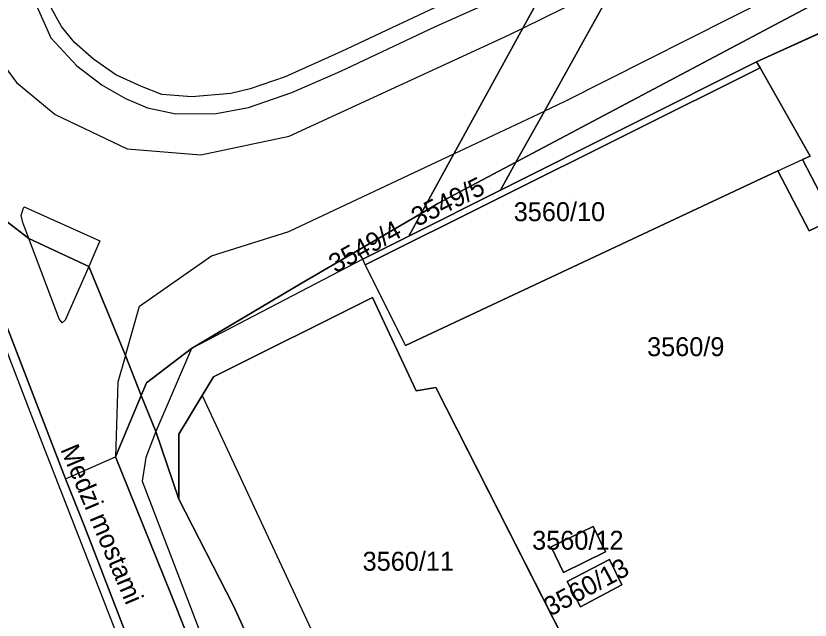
# Model space of a CAD drawing. Extents: x -262657 to -261595, y -1238015 to -1237156.
# Drawn here: x -262558.2 to -262474.2, y -1237300.9 to -1237237.1 of the extents above; entities that cross this region are included whole.
import ezdxf

# ---------------------------------------------------------------- set-up
doc = ezdxf.new("R2010")
doc.units = 0
for name, color, linetype in [('body_kn', 7, 'Continuous'), ('kladpar_druhypozemkov', 7, 'Continuous'), ('kladpar_hranice', 7, 'Continuous'), ('kladpar_parcelnecisla', 7, 'Continuous'), ('kladpar_plochy', 7, 'Continuous'), ('popisy', 7, 'Continuous'), ('zappar_hrandruhpozemk', 7, 'Continuous')]:
    doc.layers.add(name, color=color, linetype=linetype)

msp = doc.modelspace()

# ---------------------------------------------------------------- linework, layer by layer
at = {"layer": 'body_kn'}
for p, q in [((-262553.39, -1237238.2), (-262553.39, -1237238.2)), ((-262518.45, -1237238.33), (-262518.45, -1237238.33)), ((-262513.82, -1237238.2), (-262513.82, -1237238.2)), ((-262504.59, -1237238.36), (-262504.59, -1237238.36)), ((-262504.59, -1237238.36), (-262504.59, -1237238.36)), ((-262554.54, -1237239.38), (-262554.54, -1237239.38)), ((-262506.03, -1237239.07), (-262506.03, -1237239.07)), ((-262552.03, -1237239.9), (-262552.03, -1237239.9)), ((-262523.79, -1237240.82), (-262523.79, -1237240.82)), ((-262551.76, -1237242.35), (-262551.76, -1237242.35)), ((-262550.02, -1237241.66), (-262550.02, -1237241.66)), ((-262479.86, -1237241.92), (-262479.86, -1237241.92)), ((-262523.85, -1237242.92), (-262523.85, -1237242.92)), ((-262479.48, -1237242.55), (-262479.48, -1237242.55)), ((-262547.63, -1237243.31), (-262547.63, -1237243.31)), ((-262529.75, -1237243.5), (-262529.75, -1237243.5)), ((-262558.17, -1237244.12), (-262558.17, -1237244.12)), ((-262549.08, -1237244.4), (-262549.08, -1237244.4)), ((-262544.93, -1237244.55), (-262544.93, -1237244.55)), ((-262533.44, -1237244.78), (-262533.44, -1237244.78)), ((-262542.78, -1237245.39), (-262542.78, -1237245.39)), ((-262539.62, -1237245.64), (-262539.62, -1237245.64)), ((-262535.47, -1237245.28), (-262535.47, -1237245.28)), ((-262529.04, -1237245.18), (-262529.04, -1237245.18)), ((-262546.63, -1237245.81), (-262546.63, -1237245.81)), ((-262500.14, -1237246.11), (-262500.14, -1237246.11)), ((-262500.14, -1237246.11), (-262500.14, -1237246.11)), ((-262544.28, -1237246.79), (-262544.28, -1237246.79)), ((-262537.02, -1237247.38), (-262537.02, -1237247.38)), ((-262533.61, -1237246.77), (-262533.61, -1237246.77)), ((-262502.31, -1237247.13), (-262502.31, -1237247.13)), ((-262554.06, -1237247.5), (-262554.06, -1237247.5)), ((-262541.29, -1237247.44), (-262541.29, -1237247.44)), ((-262529.31, -1237249.79), (-262529.31, -1237249.79)), ((-262546.46, -1237251.13), (-262546.46, -1237251.13)), ((-262538.64, -1237251.75), (-262538.64, -1237251.75)), ((-262511.88, -1237251.65), (-262511.88, -1237251.65)), ((-262511.88, -1237251.65), (-262511.88, -1237251.65)), ((-262474.99, -1237252.26), (-262474.99, -1237252.26)), ((-262474.21, -1237251.89), (-262474.21, -1237251.89)), ((-262505.32, -1237252.54), (-262505.32, -1237252.54)), ((-262477.6, -1237253.45), (-262477.6, -1237253.45)), ((-262477.6, -1237253.45), (-262477.6, -1237253.45)), ((-262506.96, -1237255.49), (-262506.96, -1237255.49)), ((-262506.96, -1237255.49), (-262506.96, -1237255.49)), ((-262557.44, -1237257.47), (-262557.44, -1237257.47)), ((-262557.33, -1237257.26), (-262557.33, -1237257.26)), ((-262513.57, -1237256.92), (-262513.57, -1237256.92)), ((-262557.65, -1237258.17), (-262557.65, -1237258.17)), ((-262515.34, -1237257.95), (-262515.34, -1237257.95)), ((-262515.34, -1237257.95), (-262515.34, -1237257.95)), ((-262557.5, -1237258.9), (-262557.5, -1237258.9)), ((-262529.33, -1237259.88), (-262529.33, -1237259.88)), ((-262474.31, -1237259.79), (-262474.31, -1237259.79)), ((-262556.86, -1237260.6), (-262556.86, -1237260.6)), ((-262556.86, -1237260.6), (-262556.86, -1237260.6)), ((-262549.35, -1237260.86), (-262549.35, -1237260.86)), ((-262516.66, -1237260.35), (-262516.66, -1237260.35)), ((-262516.66, -1237260.35), (-262516.66, -1237260.35)), ((-262537.51, -1237262.43), (-262537.51, -1237262.43)), ((-262522.11, -1237261.89), (-262522.11, -1237261.89)), ((-262521.53, -1237262.79), (-262521.53, -1237262.79)), ((-262521.53, -1237262.79), (-262521.53, -1237262.79)), ((-262521.26, -1237263.38), (-262521.26, -1237263.38)), ((-262521.26, -1237263.38), (-262521.26, -1237263.38)), ((-262550.52, -1237263.55), (-262550.52, -1237263.55)), ((-262550.52, -1237263.55), (-262550.52, -1237263.55)), ((-262527.92, -1237265.28), (-262527.92, -1237265.28)), ((-262520.5, -1237266.83), (-262520.5, -1237266.83)), ((-262545.14, -1237267.77), (-262545.14, -1237267.77)), ((-262553.65, -1237269.09), (-262553.65, -1237269.09)), ((-262553.65, -1237269.09), (-262553.65, -1237269.09)), ((-262553, -1237269.23), (-262553, -1237269.23)), ((-262553.33, -1237269.53), (-262553.33, -1237269.53)), ((-262539.65, -1237272.22), (-262539.65, -1237272.22)), ((-262539.65, -1237272.22), (-262539.65, -1237272.22)), ((-262516.99, -1237271.93), (-262516.99, -1237271.93)), ((-262546.64, -1237272.98), (-262546.64, -1237272.98)), ((-262546.64, -1237272.98), (-262546.64, -1237272.98)), ((-262547.45, -1237275.8), (-262547.45, -1237275.8)), ((-262544.39, -1237275.85), (-262544.39, -1237275.85)), ((-262537.33, -1237275.21), (-262537.33, -1237275.21)), ((-262515.86, -1237276.71), (-262515.86, -1237276.71)), ((-262513.79, -1237276.37), (-262513.79, -1237276.37)), ((-262544.97, -1237277.21), (-262544.97, -1237277.21)), ((-262544.97, -1237277.21), (-262544.97, -1237277.21)), ((-262538.53, -1237277.21), (-262538.53, -1237277.21)), ((-262538.53, -1237277.21), (-262538.53, -1237277.21)), ((-262556.56, -1237279.36), (-262556.56, -1237279.36)), ((-262543.4, -1237280.99), (-262543.4, -1237280.99)), ((-262543.4, -1237280.99), (-262543.4, -1237280.99)), ((-262540.98, -1237281.3), (-262540.98, -1237281.3)), ((-262547.68, -1237283.68), (-262547.68, -1237283.68)), ((-262544.46, -1237283.76), (-262544.46, -1237283.76)), ((-262552.98, -1237286.01), (-262552.98, -1237286.01)), ((-262552.98, -1237286.01), (-262552.98, -1237286.01)), ((-262544.85, -1237286.26), (-262544.85, -1237286.26)), ((-262540.97, -1237288.14), (-262540.97, -1237288.14)), ((-262550.94, -1237291.12), (-262550.94, -1237291.12)), ((-262497.15, -1237291.03), (-262497.15, -1237291.03)), ((-262501.6, -1237293.21), (-262501.6, -1237293.21)), ((-262495.83, -1237293.72), (-262495.83, -1237293.72)), ((-262495.43, -1237294.53), (-262495.43, -1237294.53)), ((-262495.43, -1237294.53), (-262495.43, -1237294.53)), ((-262500.28, -1237295.9), (-262500.28, -1237295.9)), ((-262500.28, -1237295.9), (-262500.28, -1237295.9)), ((-262499.89, -1237296.87), (-262499.89, -1237296.87)), ((-262494.11, -1237297.23), (-262494.11, -1237297.23)), ((-262541.83, -1237298.18), (-262541.83, -1237298.18)), ((-262535.24, -1237299.36), (-262535.24, -1237299.36)), ((-262498.5, -1237299.53), (-262498.5, -1237299.53))]:
    msp.add_line(p, q, dxfattribs=at)
at = {"layer": 'kladpar_druhypozemkov'}
for p, q in [((-262508.03, -1237255.36), (-262508.03, -1237255.36)), ((-262499.28, -1237255.99), (-262499.28, -1237255.99)), ((-262517.11, -1237260.11), (-262517.11, -1237260.11)), ((-262487.22, -1237270.93), (-262487.22, -1237270.93)), ((-262497.91, -1237291.76), (-262497.91, -1237291.76)), ((-262516.8, -1237293.31), (-262516.8, -1237293.31)), ((-262496.67, -1237295.82), (-262496.67, -1237295.82))]:
    msp.add_line(p, q, dxfattribs=at)
at = {"layer": 'kladpar_hranice'}
for p, q in [((-262505.32, -1237252.54), (-262506.96, -1237255.49)), ((-262506.96, -1237255.49), (-262505.32, -1237252.54)), ((-262506.96, -1237255.49), (-262516.66, -1237260.35)), ((-262516.66, -1237260.35), (-262515.34, -1237257.95)), ((-262515.34, -1237257.95), (-262516.66, -1237260.35))]:
    msp.add_line(p, q, dxfattribs=at)
for points in [[(-262423.24, -1237160.61), (-262417.1, -1237160.14), (-262414.59, -1237159.95), (-262411.72, -1237159.74), (-262404.24, -1237159.17), (-262402.21, -1237159.02), (-262389.58, -1237158.25), (-262389.53, -1237160.15), (-262388.87, -1237171.3), (-262388.75, -1237173.56), (-262401.4, -1237174.26), (-262401.05, -1237180.06), (-262405.56, -1237191.01), (-262411.31, -1237199.63), (-262419.14, -1237206.33), (-262447.54, -1237221.87), (-262505.32, -1237252.54)], [(-262505.32, -1237252.54), (-262502.31, -1237247.13), (-262494.71, -1237233.49), (-262491.75, -1237228.16), (-262490.04, -1237225.08), (-262484.1, -1237214.42), (-262472.68, -1237193.89), (-262463.41, -1237193.1), (-262451.2, -1237197.46), (-262446.68, -1237189.71), (-262443.64, -1237183.82), (-262442, -1237180.62), (-262439.44, -1237175.67), (-262439.11, -1237175.02), (-262433.18, -1237163.52), (-262432.03, -1237161.27)], [(-262456.94, -1237165.58), (-262465.52, -1237181.01), (-262472.68, -1237193.89), (-262484.1, -1237214.42), (-262490.04, -1237225.08), (-262491.75, -1237228.16), (-262494.71, -1237233.49), (-262502.31, -1237247.13), (-262505.32, -1237252.54)], [(-262515.34, -1237257.95), (-262511.88, -1237251.65), (-262504.59, -1237238.36), (-262501.45, -1237232.64), (-262499.77, -1237229.58), (-262474.19, -1237182.99), (-262464.99, -1237166.22)], [(-262474.19, -1237182.99), (-262499.77, -1237229.58), (-262501.45, -1237232.64), (-262504.59, -1237238.36), (-262511.88, -1237251.65), (-262515.34, -1237257.95)], [(-262505.32, -1237252.54), (-262447.54, -1237221.87), (-262443.59, -1237224.37), (-262470.35, -1237237.61), (-262479.86, -1237241.92), (-262506.96, -1237255.49)], [(-262471.71, -1237258.55), (-262474.99, -1237252.26), (-262474.21, -1237251.89), (-262479.48, -1237242.55), (-262479.86, -1237241.92), (-262470.35, -1237237.61)], [(-262544.97, -1237277.21), (-262544.39, -1237275.85), (-262539.65, -1237272.22), (-262527.92, -1237265.28), (-262522.11, -1237261.89), (-262521.53, -1237262.79), (-262516.66, -1237260.35), (-262506.96, -1237255.49), (-262479.86, -1237241.92), (-262479.48, -1237242.55), (-262521.26, -1237263.38), (-262516.99, -1237271.93), (-262477.6, -1237253.45), (-262474.31, -1237259.79), (-262471.71, -1237258.55)], [(-262471.71, -1237258.55), (-262474.31, -1237259.79), (-262477.6, -1237253.45), (-262516.99, -1237271.93), (-262521.26, -1237263.38), (-262479.48, -1237242.55), (-262474.21, -1237251.89), (-262474.99, -1237252.26), (-262471.71, -1237258.55)], [(-262574.37, -1237249.46), (-262568.63, -1237248.12), (-262568.05, -1237247.91), (-262567.35, -1237249.24), (-262566.74, -1237250.59), (-262564.55, -1237256.82), (-262558.85, -1237270.72), (-262552.98, -1237286.01), (-262550.94, -1237291.12), (-262542.72, -1237312.39), (-262540.2, -1237319.46), (-262538.34, -1237323.9), (-262536.56, -1237330.58), (-262531.33, -1237349.62), (-262532.04, -1237349.98), (-262533.34, -1237350.65), (-262556.43, -1237362.71), (-262558.44, -1237358.79), (-262564.27, -1237347.05)], [(-262566.74, -1237250.59), (-262563.3, -1237255.68), (-262556.86, -1237260.6), (-262550.52, -1237263.55), (-262546.64, -1237272.98), (-262544.97, -1237277.21)], [(-262544.97, -1237277.21), (-262547.68, -1237283.68), (-262541.83, -1237298.18), (-262537.2, -1237309.76), (-262532.89, -1237321.1), (-262529.29, -1237326.85), (-262525.82, -1237331.27), (-262522.72, -1237333.28), (-262518.85, -1237334.11), (-262515.3, -1237341.44), (-262526.44, -1237347.1), (-262531.33, -1237349.62), (-262536.56, -1237330.58), (-262538.34, -1237323.9), (-262540.2, -1237319.46), (-262542.72, -1237312.39), (-262550.94, -1237291.12), (-262552.98, -1237286.01), (-262558.85, -1237270.72), (-262564.55, -1237256.82), (-262566.74, -1237250.59)], [(-262544.97, -1237277.21), (-262546.64, -1237272.98), (-262550.52, -1237263.55), (-262556.86, -1237260.6), (-262563.3, -1237255.68), (-262566.74, -1237250.59)], [(-262505.32, -1237252.54), (-262513.57, -1237256.92), (-262515.34, -1237257.95)], [(-262515.34, -1237257.95), (-262513.57, -1237256.92), (-262505.32, -1237252.54)], [(-262515.34, -1237257.95), (-262522.11, -1237261.89), (-262527.92, -1237265.28), (-262539.65, -1237272.22), (-262544.39, -1237275.85), (-262544.97, -1237277.21)], [(-262516.66, -1237260.35), (-262521.53, -1237262.79), (-262522.11, -1237261.89), (-262515.34, -1237257.95)], [(-262470.96, -1237307.46), (-262485.02, -1237316.52), (-262484.59, -1237318.04), (-262489.43, -1237320.89), (-262505.64, -1237329.92), (-262506.56, -1237329.35), (-262518.85, -1237334.11), (-262519.91, -1237332.2), (-262521.33, -1237329.6), (-262515.41, -1237326.75), (-262496.12, -1237317.47), (-262499.6, -1237311.25), (-262496.96, -1237309.42), (-262513.79, -1237276.37), (-262515.86, -1237276.71), (-262520.5, -1237266.83), (-262537.33, -1237275.21), (-262538.53, -1237277.21), (-262540.98, -1237281.3), (-262540.97, -1237288.14), (-262543.4, -1237280.99), (-262544.97, -1237277.21)], [(-262521.33, -1237329.6), (-262535.24, -1237299.36), (-262540.97, -1237288.14), (-262540.98, -1237281.3), (-262538.53, -1237277.21), (-262537.33, -1237275.21), (-262520.5, -1237266.83), (-262515.86, -1237276.71), (-262513.79, -1237276.37), (-262496.96, -1237309.42), (-262499.6, -1237311.25), (-262496.12, -1237317.47), (-262515.41, -1237326.75), (-262521.33, -1237329.6)], [(-262521.33, -1237329.6), (-262519.91, -1237332.2), (-262518.85, -1237334.11), (-262522.72, -1237333.28), (-262525.82, -1237331.27), (-262529.29, -1237326.85), (-262532.89, -1237321.1), (-262537.2, -1237309.76), (-262541.83, -1237298.18), (-262547.68, -1237283.68), (-262544.97, -1237277.21), (-262543.4, -1237280.99), (-262540.97, -1237288.14), (-262535.24, -1237299.36), (-262521.33, -1237329.6)], [(-262501.6, -1237293.21), (-262500.28, -1237295.9), (-262495.83, -1237293.72), (-262497.15, -1237291.03), (-262501.6, -1237293.21)], [(-262500.28, -1237295.9), (-262501.6, -1237293.21), (-262497.15, -1237291.03), (-262495.83, -1237293.72), (-262500.28, -1237295.9)], [(-262494.11, -1237297.23), (-262495.43, -1237294.53), (-262499.89, -1237296.87), (-262498.5, -1237299.53), (-262494.11, -1237297.23)], [(-262495.43, -1237294.53), (-262494.11, -1237297.23), (-262498.5, -1237299.53), (-262499.89, -1237296.87), (-262495.43, -1237294.53)]]:
    msp.add_lwpolyline(points, dxfattribs=at)
at = {"layer": 'kladpar_plochy'}
for p, q in [((-262479.86, -1237241.92), (-262470.35, -1237237.61)), ((-262506.96, -1237255.49), (-262479.86, -1237241.92)), ((-262479.86, -1237241.92), (-262479.48, -1237242.55)), ((-262479.48, -1237242.55), (-262479.86, -1237241.92)), ((-262479.48, -1237242.55), (-262521.26, -1237263.38)), ((-262474.21, -1237251.89), (-262479.48, -1237242.55)), ((-262474.99, -1237252.26), (-262474.21, -1237251.89)), ((-262471.71, -1237258.55), (-262474.99, -1237252.26)), ((-262516.99, -1237271.93), (-262477.6, -1237253.45)), ((-262477.6, -1237253.45), (-262474.31, -1237259.79)), ((-262516.66, -1237260.35), (-262506.96, -1237255.49)), ((-262474.31, -1237259.79), (-262471.71, -1237258.55)), ((-262521.53, -1237262.79), (-262516.66, -1237260.35)), ((-262527.92, -1237265.28), (-262522.11, -1237261.89)), ((-262522.11, -1237261.89), (-262521.53, -1237262.79)), ((-262521.26, -1237263.38), (-262516.99, -1237271.93)), ((-262539.65, -1237272.22), (-262527.92, -1237265.28)), ((-262520.5, -1237266.83), (-262537.33, -1237275.21)), ((-262515.86, -1237276.71), (-262520.5, -1237266.83)), ((-262558.85, -1237270.72), (-262552.98, -1237286.01)), ((-262544.39, -1237275.85), (-262539.65, -1237272.22)), ((-262544.97, -1237277.21), (-262544.39, -1237275.85)), ((-262537.33, -1237275.21), (-262538.53, -1237277.21)), ((-262513.79, -1237276.37), (-262515.86, -1237276.71)), ((-262496.96, -1237309.42), (-262513.79, -1237276.37)), ((-262543.4, -1237280.99), (-262544.97, -1237277.21)), ((-262538.53, -1237277.21), (-262540.98, -1237281.3)), ((-262540.97, -1237288.14), (-262543.4, -1237280.99)), ((-262540.98, -1237281.3), (-262540.97, -1237288.14)), ((-262552.98, -1237286.01), (-262550.94, -1237291.12)), ((-262550.94, -1237291.12), (-262542.72, -1237312.39)), ((-262497.15, -1237291.03), (-262501.6, -1237293.21)), ((-262495.83, -1237293.72), (-262497.15, -1237291.03)), ((-262501.6, -1237293.21), (-262500.28, -1237295.9)), ((-262500.28, -1237295.9), (-262495.83, -1237293.72)), ((-262495.43, -1237294.53), (-262499.89, -1237296.87)), ((-262494.11, -1237297.23), (-262495.43, -1237294.53)), ((-262499.89, -1237296.87), (-262498.5, -1237299.53)), ((-262498.5, -1237299.53), (-262494.11, -1237297.23))]:
    msp.add_line(p, q, dxfattribs=at)
for points in [[(-262464.99, -1237166.22), (-262457.28, -1237165.61), (-262456.94, -1237165.58), (-262465.52, -1237181.01), (-262472.68, -1237193.89), (-262484.1, -1237214.42), (-262490.04, -1237225.08), (-262491.75, -1237228.16), (-262494.71, -1237233.49), (-262502.31, -1237247.13), (-262505.32, -1237252.54), (-262513.57, -1237256.92), (-262515.34, -1237257.95), (-262511.88, -1237251.65), (-262504.59, -1237238.36), (-262501.45, -1237232.64), (-262499.77, -1237229.58), (-262474.19, -1237182.99)], [(-262506.96, -1237255.49), (-262505.32, -1237252.54), (-262447.54, -1237221.87), (-262443.59, -1237224.37), (-262470.35, -1237237.61), (-262479.86, -1237241.92)], [(-262471.71, -1237258.55), (-262474.31, -1237259.79), (-262477.6, -1237253.45), (-262516.99, -1237271.93), (-262521.26, -1237263.38), (-262479.48, -1237242.55), (-262474.21, -1237251.89), (-262474.99, -1237252.26)], [(-262515.34, -1237257.95), (-262513.57, -1237256.92), (-262505.32, -1237252.54), (-262506.96, -1237255.49), (-262516.66, -1237260.35)], [(-262516.66, -1237260.35), (-262521.53, -1237262.79), (-262522.11, -1237261.89), (-262515.34, -1237257.95)], [(-262521.33, -1237329.6), (-262535.24, -1237299.36), (-262540.97, -1237288.14), (-262540.98, -1237281.3), (-262538.53, -1237277.21), (-262537.33, -1237275.21), (-262520.5, -1237266.83), (-262515.86, -1237276.71), (-262513.79, -1237276.37), (-262496.96, -1237309.42), (-262499.6, -1237311.25), (-262496.12, -1237317.47), (-262515.41, -1237326.75)], [(-262521.33, -1237329.6), (-262519.91, -1237332.2), (-262518.85, -1237334.11), (-262522.72, -1237333.28), (-262525.82, -1237331.27), (-262529.29, -1237326.85), (-262532.89, -1237321.1), (-262537.2, -1237309.76), (-262541.83, -1237298.18), (-262547.68, -1237283.68), (-262544.97, -1237277.21), (-262543.4, -1237280.99), (-262540.97, -1237288.14), (-262535.24, -1237299.36)], [(-262500.28, -1237295.9), (-262501.6, -1237293.21), (-262497.15, -1237291.03), (-262495.83, -1237293.72)], [(-262495.43, -1237294.53), (-262494.11, -1237297.23), (-262498.5, -1237299.53), (-262499.89, -1237296.87)]]:
    msp.add_lwpolyline(points, close=True, dxfattribs=at)
for points in [[(-262447.54, -1237221.87), (-262505.32, -1237252.54), (-262502.31, -1237247.13), (-262494.71, -1237233.49), (-262491.75, -1237228.16), (-262490.04, -1237225.08), (-262484.1, -1237214.42), (-262472.68, -1237193.89)], [(-262501.45, -1237232.64), (-262504.59, -1237238.36), (-262511.88, -1237251.65), (-262515.34, -1237257.95), (-262522.11, -1237261.89), (-262527.92, -1237265.28), (-262539.65, -1237272.22), (-262544.39, -1237275.85), (-262544.97, -1237277.21), (-262546.64, -1237272.98), (-262550.52, -1237263.55), (-262556.86, -1237260.6), (-262563.3, -1237255.68), (-262566.74, -1237250.59), (-262567.35, -1237249.24), (-262568.05, -1237247.91), (-262568.63, -1237248.12), (-262570.5, -1237245.78), (-262574.14, -1237242.68), (-262581.5, -1237241.24), (-262586.63, -1237235.33)], [(-262563.3, -1237255.68), (-262556.86, -1237260.6), (-262550.52, -1237263.55), (-262546.64, -1237272.98), (-262544.97, -1237277.21), (-262547.68, -1237283.68), (-262541.83, -1237298.18), (-262537.2, -1237309.76), (-262532.89, -1237321.1), (-262529.29, -1237326.85), (-262525.82, -1237331.27), (-262522.72, -1237333.28), (-262518.85, -1237334.11), (-262515.3, -1237341.44), (-262526.44, -1237347.1), (-262531.33, -1237349.62), (-262536.56, -1237330.58), (-262538.34, -1237323.9), (-262540.2, -1237319.46), (-262542.72, -1237312.39), (-262550.94, -1237291.12), (-262552.98, -1237286.01), (-262558.85, -1237270.72)]]:
    msp.add_lwpolyline(points, dxfattribs=at)
at = {"layer": 'zappar_hrandruhpozemk'}
for p, q in [((-262443.35, -1237217.48), (-262500.14, -1237246.11)), ((-262513.82, -1237238.2), (-262501.45, -1237232.64)), ((-262504.59, -1237238.36), (-262494.71, -1237233.49)), ((-262550.02, -1237241.66), (-262552.03, -1237239.9)), ((-262558.17, -1237244.12), (-262554.06, -1237247.5)), ((-262500.14, -1237246.11), (-262502.31, -1237247.13)), ((-262511.88, -1237251.65), (-262502.31, -1237247.13)), ((-262568.63, -1237248.12), (-262556.56, -1237279.36)), ((-262529.33, -1237259.88), (-262511.88, -1237251.65)), ((-262477.6, -1237253.45), (-262474.99, -1237252.26)), ((-262557.33, -1237257.26), (-262549.35, -1237260.86)), ((-262537.51, -1237262.43), (-262529.33, -1237259.88)), ((-262553.65, -1237269.09), (-262556.86, -1237260.6)), ((-262549.35, -1237260.86), (-262550.52, -1237263.55)), ((-262521.53, -1237262.79), (-262539.65, -1237272.22)), ((-262521.26, -1237263.38), (-262521.53, -1237262.79)), ((-262539.65, -1237272.22), (-262543.4, -1237280.99)), ((-262546.64, -1237272.98), (-262547.45, -1237275.8)), ((-262547.45, -1237275.8), (-262547.68, -1237283.68)), ((-262538.53, -1237277.21), (-262515.41, -1237326.75)), ((-262556.56, -1237279.36), (-262544.72, -1237309.65)), ((-262552.98, -1237286.01), (-262547.68, -1237283.68))]:
    msp.add_line(p, q, dxfattribs=at)
for points in [[(-262543.28, -1237201.38), (-262546.89, -1237202.74), (-262550.81, -1237204.57), (-262553.58, -1237206.1), (-262556.18, -1237207.76), (-262558, -1237209.23), (-262559.59, -1237210.84), (-262561.47, -1237213.31), (-262563.24, -1237216.53), (-262564.32, -1237219.67), (-262565.17, -1237223.44), (-262565.56, -1237226.83), (-262565.35, -1237230.44), (-262563.43, -1237236.04), (-262561.43, -1237239.7), (-262558.17, -1237244.12)], [(-262552.03, -1237239.9), (-262553.39, -1237238.2), (-262554.65, -1237235.92), (-262555.55, -1237233.56), (-262556.2, -1237231), (-262556.34, -1237228.41), (-262556.07, -1237224.76), (-262555.32, -1237221.56), (-262557.04, -1237226.4), (-262557.33, -1237229.26), (-262557.1, -1237231.86), (-262556.26, -1237235.5), (-262554.54, -1237239.38), (-262551.76, -1237242.35), (-262549.08, -1237244.4), (-262546.63, -1237245.81), (-262544.28, -1237246.79), (-262541.29, -1237247.44), (-262537.02, -1237247.38), (-262533.61, -1237246.77), (-262529.04, -1237245.18), (-262523.85, -1237242.92), (-262513.82, -1237238.2)], [(-262499.77, -1237229.58), (-262504.84, -1237231.92), (-262518.45, -1237238.33), (-262523.79, -1237240.82), (-262529.75, -1237243.5), (-262533.44, -1237244.78), (-262535.47, -1237245.28), (-262539.62, -1237245.64), (-262542.78, -1237245.39), (-262544.93, -1237244.55), (-262547.63, -1237243.31), (-262550.02, -1237241.66)], [(-262554.06, -1237247.5), (-262546.46, -1237251.13), (-262538.64, -1237251.75), (-262529.31, -1237249.79), (-262506.03, -1237239.07), (-262504.59, -1237238.36)], [(-262556.86, -1237260.6), (-262557.5, -1237258.9), (-262557.65, -1237258.17), (-262557.44, -1237257.47), (-262557.33, -1237257.26)], [(-262546.64, -1237272.98), (-262545.14, -1237267.77), (-262537.51, -1237262.43)], [(-262550.52, -1237263.55), (-262553, -1237269.23), (-262553.33, -1237269.53), (-262553.65, -1237269.09)], [(-262543.4, -1237280.99), (-262544.46, -1237283.76), (-262544.85, -1237286.26)], [(-262544.85, -1237286.26), (-262535.97, -1237309.42), (-262531.44, -1237320.74)]]:
    msp.add_lwpolyline(points, dxfattribs=at)

# ---------------------------------------------------------------- texts
at = {"layer": 'kladpar_parcelnecisla'}
for s, rotation, p in [('3549/5', 26, (-262515.772, -1237259.388)), ('3549/4', 29, (-262524.415, -1237264.312)), ('3560/13', 28, (-262501.695, -1237300.585))]:
    msp.add_text(s, height=2, rotation=rotation, dxfattribs=at).set_placement(p)
for s, p in [('3560/10', (-262505.552, -1237258.77)), ('3560/9', (-262491.449, -1237273.04)), ('3560/12', (-262503.607, -1237293.5)), ('3560/11', (-262521.541, -1237295.72))]:
    msp.add_text(s, height=2, dxfattribs=at).set_placement(p)
at = {"layer": 'popisy'}
msp.add_text('Medzi mostami', height=2, rotation=293, dxfattribs=at).set_placement((-262553.542, -1237282.899))

doc.saveas('drawing.dxf')
